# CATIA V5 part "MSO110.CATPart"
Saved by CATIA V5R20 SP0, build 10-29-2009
Part number: MSO110
Definition: NONE
Nomenclature: MSO110
Source: Unknown
Description: MSO110
Bounding box of the stored display mesh (mm): x 0 to 12, y -5 to 5, z -5 to 5
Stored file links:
  C:\Users\Utente\Desktop\IO LAVORO\3D X SITO CF\X SITO\PLASTICA\CFMR\MSO110.CATPart
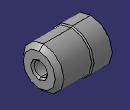
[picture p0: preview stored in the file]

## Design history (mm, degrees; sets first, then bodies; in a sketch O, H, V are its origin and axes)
Body1 "MSO110" (main body)
  Solid1: solid without history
